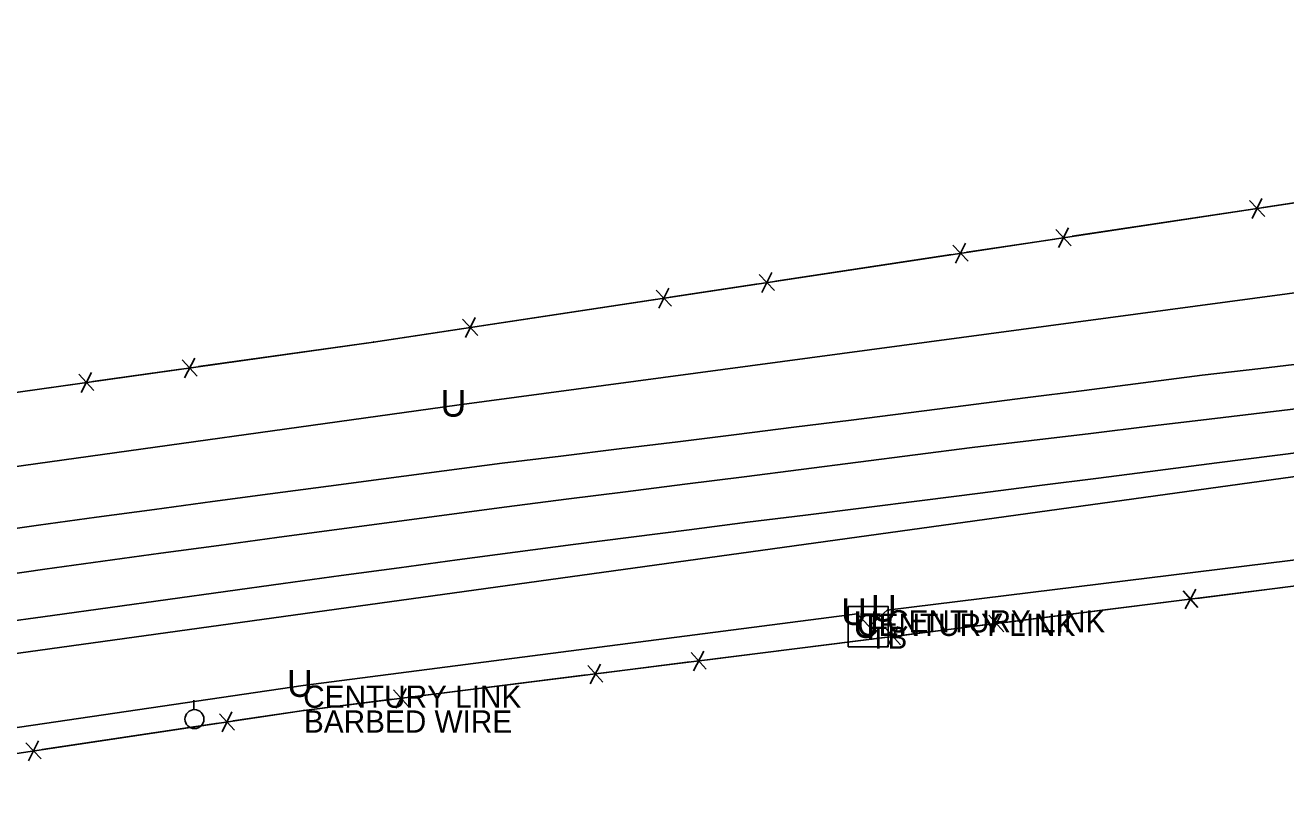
# Model space of a CAD drawing. Extents: x 1568433 to 1572450, y 731863 to 733450.
# Drawn here: x 1569982.8 to 1570266.2, y 732125.2 to 732301.5 of the extents above; entities that cross this region are included whole.
import ezdxf

# ---------------------------------------------------------------- set-up
doc = ezdxf.new("R2010")
doc.units = 0
for name, color, linetype in [('Default', 7, 'Continuous'), ('S_BASELINE', 7, 'Continuous'), ('S_EDGE_PAVEMENT', 7, 'Continuous'), ('S_FENCE', 7, 'Continuous'), ('S_FENCE_ANNOT', 7, 'Continuous'), ('S_MSC_PT_SYM', 7, 'Continuous'), ('S_PAVEMENT_CROWN', 7, 'Continuous'), ('S_TELEPHONE_UTILITIES', 7, 'Continuous'), ('S_TELEPHONE_UTILITIES_ANNOT', 7, 'Continuous'), ('S_UNDERGROUND_CABLE', 7, 'Continuous'), ('S_UNDERGROUND_CABLE_ANNOT', 7, 'Continuous'), ('S_UTILITY_POLE', 7, 'Continuous')]:
    doc.layers.add(name, color=color, linetype=linetype)

msp = doc.modelspace()

# ---------------------------------------------------------------- linework, layer by layer
at = {"layer": 'S_BASELINE'}
msp.add_line((1569838.9, 732140.65), (1570488.07, 732230.45), dxfattribs=at)
at = {"layer": 'S_EDGE_PAVEMENT'}
for points in [[(1569972.73, 732187.27), (1569985.84, 732189.13), (1569998.86, 732190.89), (1570011.89, 732192.66), (1570024.92, 732194.42), (1570037.94, 732196.19), (1570050.98, 732197.9), (1570064.01, 732199.61), (1570077.04, 732201.32), (1570090.08, 732203.03), (1570103.24, 732204.65), (1570116.39, 732206.26), (1570129.55, 732207.88), (1570142.71, 732209.5), (1570155.62, 732211.12), (1570168.52, 732212.75), (1570181.42, 732214.38), (1570194.32, 732216), (1570207.6, 732217.71), (1570220.87, 732219.42), (1570234.14, 732221.13), (1570247.42, 732222.84), (1570260.59, 732224.37), (1570273.76, 732225.9)], [(1569975.8, 732167.05), (1569988.99, 732168.82), (1570001.94, 732170.63), (1570014.9, 732172.44), (1570027.86, 732174.24), (1570040.82, 732176.05), (1570053.85, 732177.81), (1570066.88, 732179.57), (1570079.91, 732181.33), (1570092.95, 732183.09), (1570106, 732184.76), (1570119.06, 732186.43), (1570132.12, 732188.11), (1570145.18, 732189.78), (1570158.27, 732191.41), (1570171.36, 732193.05), (1570184.46, 732194.68), (1570197.55, 732196.32), (1570210.85, 732198.02), (1570224.14, 732199.72), (1570237.44, 732201.43), (1570250.74, 732203.13), (1570263.78, 732204.79), (1570276.82, 732206.44)]]:
    msp.add_lwpolyline(points, dxfattribs=at)
at = {"layer": 'S_FENCE'}
for p, q in [((1570061.14, 732230.29), (1570532.01, 732301.49)), ((1570258.03, 732262.13), (1570261.48, 732258.51)), ((1570258.03, 732262.13), (1570261.48, 732258.51)), ((1570258.64, 732258.08), (1570260.87, 732262.56)), ((1570258.64, 732258.08), (1570260.87, 732262.56)), ((1570214.52, 732255.55), (1570217.97, 732251.93)), ((1570214.52, 732255.55), (1570217.97, 732251.93)), ((1570215.14, 732251.5), (1570217.36, 732255.98)), ((1570215.14, 732251.5), (1570217.36, 732255.98)), ((1570191.35, 732252.05), (1570194.8, 732248.43)), ((1570191.35, 732252.05), (1570194.8, 732248.43)), ((1570191.97, 732248), (1570194.19, 732252.48)), ((1570191.97, 732248), (1570194.19, 732252.48)), ((1570147.85, 732245.47), (1570151.3, 732241.85)), ((1570147.85, 732245.47), (1570151.3, 732241.85)), ((1570148.46, 732241.42), (1570150.68, 732245.9)), ((1570148.46, 732241.42), (1570150.68, 732245.9)), ((1570124.68, 732241.97), (1570128.13, 732238.35)), ((1570124.68, 732241.97), (1570128.13, 732238.35)), ((1570125.29, 732237.92), (1570127.51, 732242.4)), ((1570125.29, 732237.92), (1570127.51, 732242.4)), ((1570081.17, 732235.39), (1570084.62, 732231.77)), ((1570081.17, 732235.39), (1570084.62, 732231.77)), ((1570081.79, 732231.34), (1570084.01, 732235.82)), ((1570081.79, 732231.34), (1570084.01, 732235.82)), ((1569864.46, 732202.58), (1570061.14, 732230.29)), ((1570018.66, 732222.24), (1570020.93, 732226.69)), ((1570018.66, 732222.24), (1570020.93, 732226.69)), ((1570018.09, 732226.29), (1570021.5, 732222.64)), ((1570018.09, 732226.29), (1570021.5, 732222.64)), ((1569994.88, 732223.03), (1569998.29, 732219.37)), ((1569994.88, 732223.03), (1569998.29, 732219.37)), ((1569995.45, 732218.97), (1569997.72, 732223.43)), ((1569995.45, 732218.97), (1569997.72, 732223.43)), ((1570045.5, 732147.5), (1570305.16, 732180.08)), ((1570243.12, 732174.36), (1570246.48, 732170.65)), ((1570243.12, 732174.36), (1570246.48, 732170.65)), ((1570243.63, 732170.29), (1570245.97, 732174.71)), ((1570243.63, 732170.29), (1570245.97, 732174.71)), ((1570199.47, 732168.88), (1570202.82, 732165.17)), ((1570199.47, 732168.88), (1570202.82, 732165.17)), ((1570199.98, 732164.81), (1570202.31, 732169.24)), ((1570199.98, 732164.81), (1570202.31, 732169.24)), ((1570176.21, 732165.96), (1570179.57, 732162.25)), ((1570176.21, 732165.96), (1570179.57, 732162.25)), ((1570176.72, 732161.9), (1570179.06, 732166.32)), ((1570176.72, 732161.9), (1570179.06, 732166.32)), ((1570132.56, 732160.48), (1570135.91, 732156.78)), ((1570132.56, 732160.48), (1570135.91, 732156.78)), ((1570133.07, 732156.42), (1570135.4, 732160.84)), ((1570133.07, 732156.42), (1570135.4, 732160.84)), ((1570109.31, 732157.57), (1570112.66, 732153.86)), ((1570109.31, 732157.57), (1570112.66, 732153.86)), ((1570109.82, 732153.5), (1570112.15, 732157.92)), ((1570109.82, 732153.5), (1570112.15, 732157.92)), ((1570065.65, 732152.09), (1570069, 732148.38)), ((1570065.65, 732152.09), (1570069, 732148.38)), ((1570066.16, 732148.02), (1570068.49, 732152.45)), ((1570066.16, 732148.02), (1570068.49, 732152.45)), ((1569896.24, 732125.16), (1570045.5, 732147.5)), ((1570027.08, 732142.67), (1570029.31, 732147.15)), ((1570027.08, 732142.67), (1570029.31, 732147.15)), ((1570026.48, 732146.72), (1570029.92, 732143.09)), ((1570026.48, 732146.72), (1570029.92, 732143.09)), ((1569982.96, 732140.21), (1569986.41, 732136.58)), ((1569982.96, 732140.21), (1569986.41, 732136.58)), ((1569983.57, 732136.16), (1569985.8, 732140.63)), ((1569983.57, 732136.16), (1569985.8, 732140.63))]:
    msp.add_line(p, q, dxfattribs=at)
for points in [[(1570261.17, 732260.54), (1570280.95, 732263.53)], [(1570261.17, 732260.54), (1570280.95, 732263.53)], [(1570218.23, 732254.04), (1570257.78, 732260.02)], [(1570218.23, 732254.04), (1570257.78, 732260.02)], [(1570194.5, 732250.45), (1570214.27, 732253.44)], [(1570194.5, 732250.45), (1570214.27, 732253.44)], [(1570151.55, 732243.96), (1570191.1, 732249.94)], [(1570151.55, 732243.96), (1570191.1, 732249.94)], [(1570127.82, 732240.37), (1570147.6, 732243.36)], [(1570127.82, 732240.37), (1570147.6, 732243.36)], [(1570084.87, 732233.88), (1570124.42, 732239.86)], [(1570084.87, 732233.88), (1570124.42, 732239.86)], [(1570061.14, 732230.29), (1570080.92, 732233.28)], [(1570061.14, 732230.29), (1570080.92, 732233.28)], [(1570021.77, 732224.75), (1570061.14, 732230.29)], [(1570021.77, 732224.75), (1570061.14, 732230.29)], [(1569998.01, 732221.4), (1570017.81, 732224.19)], [(1569998.01, 732221.4), (1570017.81, 732224.19)], [(1569955, 732215.34), (1569994.61, 732220.92)], [(1569955, 732215.34), (1569994.61, 732220.92)], [(1570246.22, 732172.68), (1570266.07, 732175.17)], [(1570246.22, 732172.68), (1570266.07, 732175.17)], [(1570203.13, 732167.27), (1570242.82, 732172.25)], [(1570203.13, 732167.27), (1570242.82, 732172.25)], [(1570179.32, 732164.29), (1570199.16, 732166.78)], [(1570179.32, 732164.29), (1570199.16, 732166.78)], [(1570136.22, 732158.88), (1570175.91, 732163.86)], [(1570136.22, 732158.88), (1570175.91, 732163.86)], [(1570112.41, 732155.89), (1570132.25, 732158.38)], [(1570112.41, 732155.89), (1570132.25, 732158.38)], [(1570069.31, 732150.48), (1570109, 732155.46)], [(1570069.31, 732150.48), (1570109, 732155.46)], [(1570045.5, 732147.5), (1570065.34, 732149.99)], [(1570045.5, 732147.5), (1570065.34, 732149.99)], [(1570029.62, 732145.12), (1570045.5, 732147.5)], [(1570029.62, 732145.12), (1570045.5, 732147.5)], [(1569986.66, 732138.69), (1570026.22, 732144.61)], [(1569986.66, 732138.69), (1570026.22, 732144.61)]]:
    msp.add_lwpolyline(points, dxfattribs=at)
at = {"layer": 'S_MSC_PT_SYM'}
for points in [[(1570061.14, 732230.29), (1570061.14, 732230.34), (1570061.14, 732230.29), (1570061.09, 732230.29), (1570061.14, 732230.29), (1570061.14, 732230.24), (1570061.14, 732230.29), (1570061.19, 732230.29)], [(1570045.5, 732147.5), (1570045.5, 732147.55), (1570045.5, 732147.5), (1570045.45, 732147.5), (1570045.5, 732147.5), (1570045.5, 732147.45), (1570045.5, 732147.5), (1570045.55, 732147.5)]]:
    msp.add_lwpolyline(points, dxfattribs=at)
at = {"layer": 'S_PAVEMENT_CROWN'}
msp.add_lwpolyline([(1569974.3, 732177.4), (1569987.27, 732179.27), (1570000.3, 732181.04), (1570013.32, 732182.81), (1570026.35, 732184.57), (1570039.37, 732186.34), (1570052.31, 732188.07), (1570065.24, 732189.8), (1570078.17, 732191.53), (1570091.11, 732193.26), (1570104.44, 732194.94), (1570117.77, 732196.63), (1570131.1, 732198.32), (1570144.43, 732200.01), (1570157.25, 732201.65), (1570170.06, 732203.28), (1570182.88, 732204.92), (1570195.7, 732206.56), (1570209.03, 732208.16), (1570222.36, 732209.76), (1570235.69, 732211.36), (1570249.03, 732212.96), (1570262.2, 732214.54), (1570275.38, 732216.12)], dxfattribs=at)
at = {"layer": 'S_TELEPHONE_UTILITIES'}
msp.add_lwpolyline([(1570167.86, 732161.82), (1570167.86, 732170.82), (1570176.86, 732170.82), (1570176.86, 732161.82)], close=True, dxfattribs=at)
at = {"layer": 'S_UNDERGROUND_CABLE'}
for p, q in [((1570079.83, 732216.06), (1570429.57, 732263.04)), ((1569839.84, 732182.82), (1570079.83, 732216.06)), ((1570176.6, 732170.01), (1570304.92, 732185.81)), ((1570172.59, 732166.34), (1570176.6, 732170.01)), ((1570045.33, 732153.09), (1570169.88, 732169.23)), ((1570169.88, 732169.23), (1570172.59, 732166.34)), ((1569879.8, 732128.85), (1570045.33, 732153.09))]:
    msp.add_line(p, q, dxfattribs=at)
at = {"layer": 'S_UTILITY_POLE'}
msp.add_line((1570020.76, 732147.68), (1570020.76, 732149.79), dxfattribs=at)
msp.add_circle((1570020.88, 732145.54), 2.13, dxfattribs=at)

# ---------------------------------------------------------------- texts
at = {"layer": 'Default'}
for p in [(1570076.2, 732213.51), (1570166.25, 732166.69), (1570172.97, 732167.46), (1570168.96, 732163.79), (1570041.7, 732150.54)]:
    msp.add_text('U', height=6, dxfattribs=at).set_placement(p)
at = {"layer": 'S_FENCE_ANNOT'}
msp.add_text('BARBED WIRE', height=5, dxfattribs=at).set_placement((1570045.5, 732142.5))
at = {"layer": 'S_TELEPHONE_UTILITIES'}
msp.add_text('T', height=6, dxfattribs=at).set_placement((1570170.43, 732163.32))
at = {"layer": 'S_TELEPHONE_UTILITIES_ANNOT'}
msp.add_text('TB', height=5, dxfattribs=at).set_placement((1570172.59, 732161.34))
at = {"layer": 'S_UNDERGROUND_CABLE_ANNOT'}
for s, p in [('CENTURY LINK', (1570176.6, 732165.01)), ('CENTURY LINK', (1570169.88, 732164.23)), ('TB', (1570172.59, 732161.34)), ('CENTURY LINK', (1570045.33, 732148.09))]:
    msp.add_text(s, height=5, dxfattribs=at).set_placement(p)

doc.saveas('drawing.dxf')
